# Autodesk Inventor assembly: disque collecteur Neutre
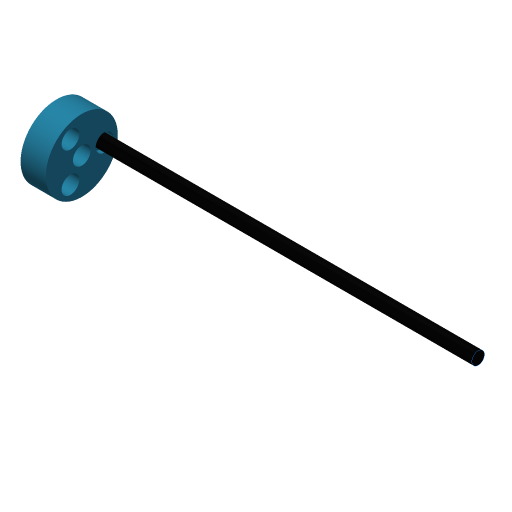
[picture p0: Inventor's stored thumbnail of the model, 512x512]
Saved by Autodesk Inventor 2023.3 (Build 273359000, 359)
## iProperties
Created: 2017-03
Part Number: disque collecteur Neutre
Document SubType Name: Assembly
Designer: thierry.jost
Author: thierry.jost
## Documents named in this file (3)
- E:\Dossier technique\Eolienne\Albra\Maquette Numerique Eolienne\214112232-CEB-Eolienne\Disque collecteur\20n-Disque collecteur Neutre.iam
- E:\Dossier technique\Eolienne\Albra\Maquette Numerique Eolienne\214112232-CEB-Eolienne\Disque collecteur\Disque collecteur n.ipt
- E:\Dossier technique\Eolienne\Albra\Maquette Numerique Eolienne\214112232-CEB-Eolienne\Disque collecteur\neutre.ipt
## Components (2 placed, 2 different names)
1. Disque collecteur n:1 — Insert:1
2. neutre:1 — Insert:1
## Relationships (1: Insert 1)
- Insert:1: Disque collecteur n:1 ↔ neutre:1
